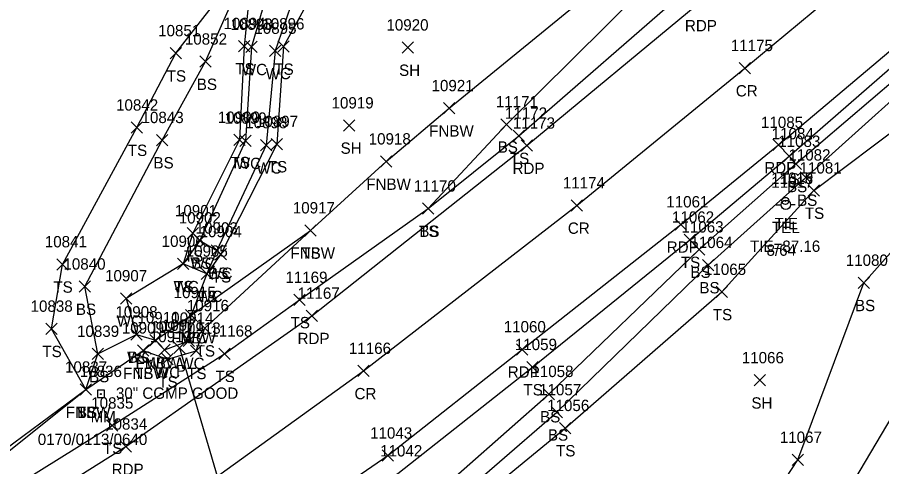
# Model space of a CAD drawing. Extents: x 1475671 to 1477951, y 592661 to 593821.
# Drawn here: x 1476588.2 to 1476740.9, y 593153.9 to 593233.2 of the extents above; entities that cross this region are included whole.
import ezdxf

# ---------------------------------------------------------------- set-up
doc = ezdxf.new("R2010")
doc.units = 0
for name, color, linetype in [('C_A', 7, 'Continuous'), ('C_C', 7, 'Continuous'), ('C_I', 7, 'Continuous'), ('CBP', 7, 'Continuous'), ('D_A', 7, 'Continuous'), ('D_C', 7, 'Continuous'), ('D_I', 7, 'Continuous'), ('D_TIC', 7, 'Continuous'), ('DCP', 7, 'Continuous'), ('L_A', 7, 'Continuous'), ('L_I', 7, 'Continuous'), ('L_TIC', 7, 'Continuous'), ('LAWE', 7, 'Continuous'), ('LELB', 7, 'Continuous'), ('LFNC', 7, 'Continuous'), ('P_A', 7, 'Continuous'), ('P_I', 7, 'Continuous'), ('P_TIC', 7, 'Continuous'), ('PET', 7, 'Continuous'), ('PRC', 7, 'Continuous'), ('S_A', 7, 'Continuous'), ('S_C', 7, 'Continuous'), ('S_I', 7, 'Continuous'), ('SRM', 7, 'Continuous'), ('U_A', 7, 'Continuous'), ('U_C', 7, 'Continuous'), ('U_I', 7, 'Continuous'), ('UP', 7, 'Continuous')]:
    doc.layers.add(name, color=color, linetype=linetype)

msp = doc.modelspace()

# ---------------------------------------------------------------- linework, layer by layer
at = {"layer": 'CBP'}
for radius in [0.625, 0.0833]:
    msp.add_circle((1476723.87, 593200.82), radius, dxfattribs=at)
at = {"layer": 'D_TIC'}
for points in [[(1476615.88, 593173.89), (1476617.88, 593175.89)], [(1476617.88, 593173.89), (1476615.88, 593175.89)]]:
    msp.add_lwpolyline(points, dxfattribs=at)
at = {"layer": 'DCP'}
msp.add_lwpolyline([(1476616.88, 593174.89), (1476630.2, 593129.6)], dxfattribs=at)
at = {"layer": 'L_TIC'}
for points in [[(1476627.33, 593227.14), (1476629.33, 593229.14)], [(1476629.33, 593227.14), (1476627.33, 593229.14)], [(1476628.57, 593227.01), (1476630.57, 593229.01)], [(1476630.57, 593227.01), (1476628.57, 593229.01)], [(1476632.78, 593226.3), (1476634.78, 593228.3)], [(1476634.78, 593226.3), (1476632.78, 593228.3)], [(1476634.23, 593227.07), (1476636.23, 593229.07)], [(1476636.23, 593227.07), (1476634.23, 593229.07)], [(1476656.18, 593226.88), (1476658.18, 593228.88)], [(1476658.18, 593226.88), (1476656.18, 593228.88)], [(1476615.22, 593225.87), (1476617.22, 593227.87)], [(1476617.22, 593225.87), (1476615.22, 593227.87)], [(1476620.5, 593224.4), (1476622.5, 593226.4)], [(1476622.5, 593224.4), (1476620.5, 593226.4)], [(1476663.49, 593216.17), (1476665.49, 593218.17)], [(1476665.49, 593216.17), (1476663.49, 593218.17)], [(1476608.35, 593212.75), (1476610.35, 593214.75)], [(1476610.35, 593212.75), (1476608.35, 593214.75)], [(1476645.84, 593213.13), (1476647.84, 593215.13)], [(1476647.84, 593213.13), (1476645.84, 593215.13)], [(1476673.63, 593213.33), (1476675.63, 593215.33)], [(1476675.63, 593213.33), (1476673.63, 593215.33)], [(1476675.81, 593211.32), (1476677.81, 593213.32)], [(1476677.81, 593211.32), (1476675.81, 593213.32)], [(1476612.85, 593210.55), (1476614.85, 593212.55)], [(1476614.85, 593210.55), (1476612.85, 593212.55)], [(1476626.49, 593210.59), (1476628.49, 593212.59)], [(1476628.49, 593210.59), (1476626.49, 593212.59)], [(1476627.52, 593210.44), (1476629.52, 593212.44)], [(1476629.52, 593210.44), (1476627.52, 593212.44)], [(1476631.16, 593209.64), (1476633.16, 593211.64)], [(1476633.16, 593209.64), (1476631.16, 593211.64)], [(1476633.06, 593209.85), (1476635.06, 593211.85)], [(1476635.06, 593209.85), (1476633.06, 593211.85)], [(1476652.4, 593206.77), (1476654.4, 593208.77)], [(1476654.4, 593206.77), (1476652.4, 593208.77)], [(1476723.55, 593207.7), (1476725.55, 593209.7)], [(1476725.55, 593207.7), (1476723.55, 593209.7)], [(1476724.71, 593206.35), (1476726.71, 593208.35)], [(1476726.71, 593206.35), (1476724.71, 593208.35)], [(1476726.5, 593203.94), (1476728.5, 593205.94)], [(1476728.5, 593203.94), (1476726.5, 593205.94)], [(1476727.9, 593201.65), (1476729.9, 593203.65)], [(1476729.9, 593201.65), (1476727.9, 593203.65)], [(1476659.79, 593198.46), (1476661.79, 593200.46)], [(1476661.79, 593198.46), (1476659.79, 593200.46)], [(1476659.79, 593198.46), (1476661.79, 593200.46)], [(1476661.79, 593198.46), (1476659.79, 593200.46)], [(1476618.26, 593194.1), (1476620.26, 593196.1)], [(1476620.26, 593194.1), (1476618.26, 593196.1)], [(1476639, 593194.61), (1476641, 593196.61)], [(1476641, 593194.61), (1476639, 593196.61)], [(1476639, 593194.61), (1476641, 593196.61)], [(1476641, 593194.61), (1476639, 593196.61)], [(1476619.49, 593192.84), (1476621.49, 593194.84)], [(1476621.49, 593192.84), (1476619.49, 593194.84)], [(1476619.49, 593192.84), (1476621.49, 593194.84)], [(1476621.49, 593192.84), (1476619.49, 593194.84)], [(1476706, 593192.97), (1476708, 593194.97)], [(1476708, 593192.97), (1476706, 593194.97)], [(1476622.48, 593191.05), (1476624.48, 593193.05)], [(1476624.48, 593191.05), (1476622.48, 593193.05)], [(1476622.48, 593191.05), (1476624.48, 593193.05)], [(1476624.48, 593191.05), (1476622.48, 593193.05)], [(1476707.67, 593191.24), (1476709.67, 593193.24)], [(1476709.67, 593191.24), (1476707.67, 593193.24)], [(1476623.18, 593190.42), (1476625.18, 593192.42)], [(1476625.18, 593190.42), (1476623.18, 593192.42)], [(1476595.2, 593188.62), (1476597.2, 593190.62)], [(1476597.2, 593188.62), (1476595.2, 593190.62)], [(1476616.53, 593188.7), (1476618.53, 593190.7)], [(1476618.53, 593188.7), (1476616.53, 593190.7)], [(1476616.53, 593188.7), (1476618.53, 593190.7)], [(1476618.53, 593188.7), (1476616.53, 593190.7)], [(1476616.53, 593188.7), (1476618.53, 593190.7)], [(1476618.53, 593188.7), (1476616.53, 593190.7)], [(1476709.24, 593188.5), (1476711.24, 593190.5)], [(1476711.24, 593188.5), (1476709.24, 593190.5)], [(1476620.73, 593186.97), (1476622.73, 593188.97)], [(1476622.73, 593186.97), (1476620.73, 593188.97)], [(1476620.73, 593186.97), (1476622.73, 593188.97)], [(1476622.73, 593186.97), (1476620.73, 593188.97)], [(1476736.72, 593185.36), (1476738.72, 593187.36)], [(1476738.72, 593185.36), (1476736.72, 593187.36)], [(1476599.14, 593184.69), (1476601.14, 593186.69)], [(1476601.14, 593184.69), (1476599.14, 593186.69)], [(1476711.65, 593183.75), (1476713.65, 593185.75)], [(1476713.65, 593183.75), (1476711.65, 593185.75)], [(1476606.49, 593182.62), (1476608.49, 593184.62)], [(1476608.49, 593182.62), (1476606.49, 593184.62)], [(1476637.09, 593182.34), (1476639.09, 593184.34)], [(1476639.09, 593182.34), (1476637.09, 593184.34)], [(1476617.95, 593179.66), (1476619.95, 593181.66)], [(1476619.95, 593179.66), (1476617.95, 593181.66)], [(1476617.95, 593179.66), (1476619.95, 593181.66)], [(1476619.95, 593179.66), (1476617.95, 593181.66)], [(1476617.95, 593179.66), (1476619.95, 593181.66)], [(1476619.95, 593179.66), (1476617.95, 593181.66)], [(1476593.26, 593177.25), (1476595.26, 593179.25)], [(1476595.26, 593177.25), (1476593.26, 593179.25)], [(1476620.33, 593177.35), (1476622.33, 593179.35)], [(1476622.33, 593177.35), (1476620.33, 593179.35)], [(1476608.32, 593176.24), (1476610.32, 593178.24)], [(1476610.32, 593176.24), (1476608.32, 593178.24)], [(1476608.32, 593176.24), (1476610.32, 593178.24)], [(1476610.32, 593176.24), (1476608.32, 593178.24)], [(1476611.65, 593175.23), (1476613.65, 593177.23)], [(1476613.65, 593175.23), (1476611.65, 593177.23)], [(1476611.65, 593175.23), (1476613.65, 593177.23)], [(1476613.65, 593175.23), (1476611.65, 593177.23)], [(1476617.55, 593175.15), (1476619.55, 593177.15)], [(1476619.55, 593175.15), (1476617.55, 593177.15)], [(1476601.47, 593172.82), (1476603.47, 593174.82)], [(1476603.47, 593172.82), (1476601.47, 593174.82)], [(1476601.47, 593172.82), (1476603.47, 593174.82)], [(1476603.47, 593172.82), (1476601.47, 593174.82)], [(1476609.45, 593173.4), (1476611.45, 593175.4)], [(1476611.45, 593173.4), (1476609.45, 593175.4)], [(1476609.45, 593173.4), (1476611.45, 593175.4)], [(1476611.45, 593173.4), (1476609.45, 593175.4)], [(1476613.24, 593173.55), (1476615.24, 593175.55)], [(1476615.24, 593173.55), (1476613.24, 593175.55)], [(1476618.83, 593173.37), (1476620.83, 593175.37)], [(1476620.83, 593173.37), (1476618.83, 593175.37)], [(1476623.83, 593172.86), (1476625.83, 593174.86)], [(1476625.83, 593172.86), (1476623.83, 593174.86)], [(1476613.74, 593171.88), (1476615.74, 593173.88)], [(1476615.74, 593171.88), (1476613.74, 593173.88)], [(1476678.21, 593170.49), (1476680.21, 593172.49)], [(1476680.21, 593170.49), (1476678.21, 593172.49)], [(1476718.38, 593168.16), (1476720.38, 593170.16)], [(1476720.38, 593168.16), (1476718.38, 593170.16)], [(1476599.34, 593166.51), (1476601.34, 593168.51)], [(1476601.34, 593166.51), (1476599.34, 593168.51)], [(1476599.34, 593166.51), (1476601.34, 593168.51)], [(1476601.34, 593166.51), (1476599.34, 593168.51)], [(1476599.34, 593166.51), (1476601.34, 593168.51)], [(1476601.34, 593166.51), (1476599.34, 593168.51)], [(1476681.12, 593165.73), (1476683.12, 593167.73)], [(1476683.12, 593165.73), (1476681.12, 593167.73)], [(1476682.5, 593162.51), (1476684.5, 593164.51)], [(1476684.5, 593162.51), (1476682.5, 593164.51)], [(1476603.97, 593160.16), (1476605.97, 593162.16)], [(1476605.97, 593160.16), (1476603.97, 593162.16)], [(1476683.96, 593159.73), (1476685.96, 593161.73)], [(1476685.96, 593159.73), (1476683.96, 593161.73)], [(1476725.04, 593154.11), (1476727.04, 593156.11)], [(1476727.04, 593154.11), (1476725.04, 593156.11)]]:
    msp.add_lwpolyline(points, dxfattribs=at)
at = {"layer": 'LAWE'}
for points in [[(1476613.09, 593353.64), (1476628.49, 593336.62), (1476629.68, 593311.25), (1476637.78, 593296.68), (1476643.29, 593273.67), (1476640.66, 593247.23), (1476633.78, 593227.3), (1476632.16, 593210.64), (1476623.48, 593192.05), (1476621.73, 593187.97), (1476618.95, 593180.66)], [(1476607.39, 593350.65), (1476623.84, 593334.1), (1476626.69, 593304.02), (1476631.08, 593291.78), (1476635.24, 593271.58), (1476635.2, 593247.29), (1476629.57, 593228.01), (1476628.52, 593211.44), (1476620.49, 593193.84), (1476617.53, 593189.7), (1476607.49, 593183.62), (1476609.32, 593177.24), (1476612.65, 593176.23), (1476614.24, 593174.55), (1476618.55, 593176.15), (1476618.95, 593180.66)]]:
    msp.add_lwpolyline(points, dxfattribs=at)
at = {"layer": 'LELB'}
for points in [[(1476660.79, 593199.46), (1476674.63, 593214.33), (1476703.92, 593243.37), (1476720.54, 593255.98), (1476751.7, 593282.61), (1476781.77, 593307.79), (1476789.04, 593316.89), (1476807.89, 593333.24), (1476839.71, 593357.28), (1476859.97, 593374.46), (1476882.16, 593391.96), (1476882.87, 593395.08), (1476884.75, 593398.78), (1476886.94, 593401.06), (1476880.92, 593405.09), (1476872.21, 593402.61), (1476869.35, 593406.91), (1476883.46, 593416.6), (1476894.87, 593423.54), (1476922.16, 593439.01), (1476941.74, 593451.3), (1476958.3, 593465.19), (1476973.77, 593478.9)], [(1476525.71, 593116.6), (1476535.99, 593117.47), (1476564.39, 593135.96), (1476604.97, 593161.16), (1476624.83, 593173.86), (1476638.09, 593183.34), (1476660.79, 593199.46), (1476676.81, 593212.32), (1476707.13, 593238.69), (1476723.81, 593252.6), (1476754.14, 593278.44), (1476785.31, 593303.01), (1476812.8, 593326.19), (1476842.99, 593352.59), (1476863.07, 593369.43), (1476886.56, 593389.77), (1476893.66, 593396.85), (1476901.2, 593401.68), (1476921.17, 593422.2)], [(1476564.12, 593090.41), (1476582.11, 593100.23), (1476611.48, 593121.39), (1476618.84, 593125.52), (1476623.35, 593128.86), (1476625.72, 593132.79), (1476629.36, 593135.67), (1476655.41, 593152.72), (1476679.21, 593171.49), (1476707, 593193.97), (1476724.55, 593208.7), (1476750.98, 593231.69), (1476770.54, 593248.26), (1476798.66, 593272.17), (1476825.82, 593296.2), (1476846.6, 593313.13), (1476851.35, 593312.9), (1476856.13, 593310.72)], [(1476631.97, 593309.46), (1476640.29, 593298.07), (1476646.83, 593274.76), (1476645.56, 593246.81), (1476635.23, 593228.07), (1476634.06, 593210.85), (1476624.18, 593191.42), (1476621.73, 593187.97), (1476617.53, 593189.7)], [(1476634.2, 593131.94), (1476659.65, 593146.95), (1476682.12, 593166.73), (1476708.67, 593192.24), (1476725.71, 593207.35), (1476752.23, 593229.94), (1476771.82, 593246.25), (1476799.29, 593271), (1476827.81, 593293.85), (1476847.08, 593308.34), (1476849.31, 593306.85)], [(1476637.68, 593129.04), (1476661.51, 593144.5), (1476683.5, 593163.51), (1476710.24, 593189.5), (1476727.5, 593204.94), (1476753.67, 593228.48), (1476773.33, 593243.8), (1476800.69, 593269.42), (1476829.36, 593291.34), (1476849.31, 593306.85)], [(1476678.64, 593101), (1476705.61, 593123.8), (1476726.04, 593155.11), (1476737.72, 593186.36), (1476761.68, 593213.28), (1476787.87, 593223.87), (1476810.46, 593252.94), (1476833.91, 593283.76), (1476845.71, 593295.92)], [(1476656.22, 593100.09), (1476649.63, 593114.77), (1476646.3, 593117.93), (1476646.01, 593122.62), (1476642.33, 593128.21), (1476662.9, 593142.59), (1476684.96, 593160.73), (1476712.65, 593184.75), (1476728.9, 593202.65), (1476756.29, 593223.25), (1476776.28, 593240.54), (1476803.27, 593265.83), (1476831.65, 593287.61)], [(1476678.64, 593101), (1476711, 593115.17), (1476731.22, 593143.42), (1476747.62, 593171.01), (1476767.46, 593198.64), (1476796.55, 593210.23), (1476815.09, 593241.8), (1476843.63, 593278.61)], [(1476600.34, 593167.51), (1476594.26, 593178.25), (1476596.2, 593189.62), (1476609.35, 593213.75), (1476616.22, 593226.87), (1476629.97, 593244.55), (1476628.33, 593228.14), (1476627.49, 593211.59), (1476619.26, 593195.1), (1476617.53, 593189.7)], [(1476602.47, 593173.82), (1476600.14, 593185.69), (1476613.85, 593211.55), (1476621.5, 593225.4), (1476629.97, 593244.55)], [(1476610.45, 593174.4), (1476614.74, 593172.88), (1476619.83, 593174.37), (1476621.33, 593178.35), (1476640, 593195.61)], [(1476620.49, 593193.84), (1476623.48, 593192.05)], [(1476498.59, 593101.6), (1476505.69, 593104.75), (1476515.32, 593111.26), (1476518.29, 593115.4), (1476532.21, 593122.02), (1476550.06, 593131.97), (1476556.63, 593136.22), (1476579.62, 593152.26), (1476600.34, 593167.51), (1476602.47, 593173.82), (1476609.32, 593177.24)]]:
    msp.add_lwpolyline(points, dxfattribs=at)
at = {"layer": 'LFNC'}
msp.add_lwpolyline([(1476458.99, 593083.01), (1476499.73, 593099.84), (1476506.4, 593103.47), (1476506.74, 593103.7), (1476516.66, 593109.69), (1476525.71, 593116.6), (1476534.13, 593120.72), (1476545.43, 593126.64), (1476563.76, 593138.28), (1476600.34, 593167.51), (1476610.45, 593174.4), (1476612.65, 593176.23), (1476618.95, 593180.66), (1476640, 593195.61), (1476653.4, 593207.77), (1476664.49, 593217.17), (1476691.69, 593239.4), (1476702.63, 593247.23), (1476709.5, 593251.9), (1476716.55, 593257.09), (1476733.12, 593270.47), (1476759.81, 593293.37)], dxfattribs=at)
at = {"layer": 'P_TIC'}
for points in [[(1476715.69, 593223.25), (1476717.69, 593225.25)], [(1476717.69, 593223.25), (1476715.69, 593225.25)], [(1476677.21, 593209.57), (1476679.21, 593211.57)], [(1476679.21, 593209.57), (1476677.21, 593211.57)], [(1476721.66, 593209.69), (1476723.66, 593211.69)], [(1476723.66, 593209.69), (1476721.66, 593211.69)], [(1476686.02, 593199.01), (1476688.02, 593201.01)], [(1476688.02, 593199.01), (1476686.02, 593201.01)], [(1476704.43, 593195.67), (1476706.43, 593197.67)], [(1476706.43, 593195.67), (1476704.43, 593197.67)], [(1476639.25, 593179.54), (1476641.25, 593181.54)], [(1476641.25, 593179.54), (1476639.25, 593181.54)], [(1476676.37, 593173.62), (1476678.37, 593175.62)], [(1476678.37, 593173.62), (1476676.37, 593175.62)], [(1476648.36, 593169.81), (1476650.36, 593171.81)], [(1476650.36, 593169.81), (1476648.36, 593171.81)], [(1476606.43, 593156.45), (1476608.43, 593158.45)], [(1476608.43, 593156.45), (1476606.43, 593158.45)], [(1476652.65, 593154.86), (1476654.65, 593156.86)], [(1476654.65, 593154.86), (1476652.65, 593156.86)]]:
    msp.add_lwpolyline(points, dxfattribs=at)
at = {"layer": 'PET'}
for points in [[(1476459.25, 593078.48), (1476508.39, 593100.17), (1476518.15, 593105.13), (1476565.38, 593131.07), (1476607.43, 593157.45), (1476640.25, 593180.54), (1476678.21, 593210.57), (1476708.64, 593235.75), (1476725.67, 593249.83), (1476755.84, 593275.3), (1476786.3, 593300.73), (1476814.32, 593324.28), (1476845.05, 593350.02), (1476865.02, 593366.82), (1476897.04, 593395.14), (1476922.98, 593419.08), (1476952.36, 593443.37)], [(1476493.61, 593061.9), (1476518.9, 593073.26), (1476550.12, 593088.22), (1476579.1, 593105.35), (1476612.57, 593127.79), (1476627.64, 593138.01), (1476653.65, 593155.86), (1476677.37, 593174.62), (1476705.43, 593196.67), (1476722.66, 593210.69), (1476749.61, 593233.45), (1476768.81, 593249.96), (1476797.5, 593274.02), (1476824.82, 593297.55), (1476845, 593315.29), (1476868.19, 593333.86), (1476888.66, 593352.98), (1476918.01, 593376.95), (1476944.23, 593398.87), (1476967.73, 593418.7), (1476998.53, 593444.47)]]:
    msp.add_lwpolyline(points, dxfattribs=at)
at = {"layer": 'PRC'}
msp.add_lwpolyline([(1476461.98, 593064.62), (1476520.7, 593090.52), (1476540.79, 593101.34), (1476577.67, 593121.61), (1476614.51, 593145.69), (1476649.36, 593170.81), (1476687.02, 593200.01), (1476716.69, 593224.25), (1476733.58, 593238.31), (1476760.9, 593261.21), (1476795.35, 593290.14), (1476823.06, 593313.51), (1476854.07, 593339.52), (1476875.7, 593357.51), (1476907.01, 593384.08), (1476934.06, 593407.68), (1476963.46, 593432.81)], dxfattribs=at)
at = {"layer": 'SRM'}
for p, q in [((1476603.65, 593167.39), (1476602.4, 593167.39)), ((1476602.4, 593167.39), (1476602.4, 593166.14)), ((1476603.65, 593167.39), (1476602.4, 593167.39)), ((1476602.4, 593167.39), (1476602.4, 593166.14)), ((1476603.65, 593166.14), (1476603.65, 593167.39)), ((1476603.65, 593166.14), (1476603.65, 593167.39)), ((1476602.4, 593166.14), (1476603.65, 593166.14)), ((1476602.4, 593166.14), (1476603.65, 593166.14))]:
    msp.add_line(p, q, dxfattribs=at)
msp.add_circle((1476603, 593166.73), 0.0833, dxfattribs=at)
at = {"layer": 'UP'}
for p, q in [((1476722.27, 593200.13), (1476723.1, 593200.13)), ((1476723.93, 593200.13), (1476723.93, 593200.13)), ((1476725.6, 593200.13), (1476724.76, 593200.13)), ((1476724.76, 593200.13), (1476724.76, 593200.13)), ((1476725.6, 593200.13), (1476725.6, 593200.13))]:
    msp.add_line(p, q, dxfattribs=at)
msp.add_circle((1476723.93, 593200.13), 0.833, dxfattribs=at)

# ---------------------------------------------------------------- texts
at = {"layer": 'C_A'}
msp.add_text('TIE', height=2, dxfattribs=at).set_placement((1476721.95, 593195.82))
at = {"layer": 'C_C'}
msp.add_text('TIE=87.16', height=2, dxfattribs=at).set_placement((1476717.61, 593191.82))
at = {"layer": 'C_I'}
msp.add_text('11018', height=2, dxfattribs=at).set_placement((1476721.34, 593203.82))
at = {"layer": 'D_A'}
msp.add_text('P', height=2, dxfattribs=at).set_placement((1476616.26, 593169.89))
at = {"layer": 'D_C'}
msp.add_text('30" CGMP GOOD', height=2, dxfattribs=at).set_placement((1476605.66, 593165.89))
at = {"layer": 'D_I'}
msp.add_text('10971', height=2, dxfattribs=at).set_placement((1476613.78, 593177.89))
at = {"layer": 'L_A'}
for s, p in [('TS', (1476626.74, 593223.14)), ('WC', (1476627.88, 593223.01)), ('TS', (1476633.64, 593223.07)), ('TS', (1476614.63, 593221.87)), ('WC', (1476632.09, 593222.3)), ('SH', (1476655.66, 593222.88)), ('BS', (1476619.94, 593220.4)), ('FNBW', (1476660.97, 593212.17)), ('BS', (1476673.07, 593209.33)), ('TS', (1476607.76, 593208.75)), ('SH', (1476645.33, 593209.13)), ('BS', (1476612.29, 593206.55)), ('TS', (1476625.9, 593206.59)), ('WC', (1476626.83, 593206.44)), ('TS', (1476675.22, 593207.32)), ('WC', (1476630.47, 593205.64)), ('TS', (1476632.47, 593205.85)), ('TS', (1476722.96, 593203.7)), ('FNBW', (1476649.87, 593202.77)), ('BS', (1476724.16, 593202.35)), ('BS', (1476725.94, 593199.94)), ('TS', (1476727.31, 593197.65)), ('TS', (1476659.2, 593194.46)), ('BS', (1476659.23, 593194.46)), ('TS', (1476617.67, 593190.1)), ('FNBW', (1476636.47, 593190.61)), ('TS', (1476638.41, 593190.61)), ('WC', (1476618.8, 593188.84)), ('BS', (1476618.94, 593188.84)), ('TS', (1476705.41, 593188.97)), ('WC', (1476621.79, 593187.05)), ('BS', (1476621.93, 593187.05)), ('TS', (1476622.59, 593186.42)), ('BS', (1476707.11, 593187.24)), ('TS', (1476594.61, 593184.62)), ('WC', (1476615.84, 593184.7)), ('TS', (1476615.94, 593184.7)), ('TS', (1476615.94, 593184.7)), ('BS', (1476708.68, 593184.5)), ('WC', (1476620.03, 593182.97)), ('TS', (1476620.13, 593182.97)), ('BS', (1476598.59, 593180.69)), ('BS', (1476736.16, 593181.36)), ('TS', (1476711.06, 593179.75)), ('WC', (1476605.8, 593178.62)), ('TS', (1476636.5, 593178.34)), ('FNBW', (1476615.43, 593175.66)), ('WC', (1476617.26, 593175.66)), ('WC', (1476617.26, 593175.66)), ('TS', (1476592.67, 593173.25)), ('TS', (1476619.74, 593173.35)), ('WC', (1476607.63, 593172.24)), ('BS', (1476607.76, 593172.24)), ('FNBW', (1476609.13, 593171.23)), ('WC', (1476610.96, 593171.23)), ('WC', (1476616.85, 593171.15)), ('BS', (1476600.91, 593168.82)), ('BS', (1476600.91, 593168.82)), ('FNBW', (1476606.93, 593169.4)), ('TS', (1476608.86, 593169.4)), ('WC', (1476612.55, 593169.55)), ('TS', (1476618.23, 593169.37)), ('TS', (1476623.24, 593168.86)), ('TS', (1476613.15, 593167.88)), ('TS', (1476677.62, 593166.49)), ('SH', (1476717.87, 593164.16)), ('FNBW', (1476596.81, 593162.51)), ('TS', (1476598.75, 593162.51)), ('BS', (1476598.78, 593162.51)), ('BS', (1476680.56, 593161.73)), ('BS', (1476681.94, 593158.51)), ('TS', (1476603.38, 593156.16)), ('TS', (1476683.37, 593155.73))]:
    msp.add_text(s, height=2, dxfattribs=at).set_placement(p)
at = {"layer": 'L_I'}
for s, p in [('10894', (1476624.66, 593231.14)), ('10893', (1476625.9, 593231.01)), ('10896', (1476631.51, 593231.07)), ('10920', (1476653.42, 593230.88)), ('10851', (1476613.11, 593229.87)), ('10895', (1476630.11, 593230.3)), ('10852', (1476617.83, 593228.4)), ('10921', (1476661.39, 593220.17)), ('10919', (1476643.73, 593217.13)), ('11171', (1476672.74, 593217.33)), ('10842', (1476605.68, 593216.75)), ('10843', (1476610.18, 593214.55)), ('10900', (1476623.65, 593214.59)), ('10899', (1476624.84, 593214.44)), ('10897', (1476630.39, 593213.85)), ('11172', (1476674.36, 593215.32)), ('10898', (1476628.49, 593213.64)), ('11084', (1476721.45, 593211.7)), ('10918', (1476650.29, 593210.77)), ('11083', (1476722.61, 593210.35)), ('11082', (1476724.4, 593207.94)), ('11081', (1476726.37, 593205.65)), ('11170', (1476658.25, 593202.46)), ('11170', (1476658.25, 593202.46)), ('10917', (1476636.89, 593198.61)), ('10917', (1476636.89, 593198.61)), ('10901', (1476616.08, 593198.1)), ('10902', (1476616.75, 593196.84)), ('10902', (1476616.75, 593196.84)), ('11062', (1476703.85, 593196.97)), ('10903', (1476619.74, 593195.05)), ('10903', (1476619.74, 593195.05)), ('10904', (1476620.43, 593194.42)), ('11063', (1476705.52, 593195.24)), ('10841', (1476593.1, 593192.62)), ('10906', (1476613.73, 593192.7)), ('10906', (1476613.73, 593192.7)), ('10906', (1476613.73, 593192.7)), ('11064', (1476707.09, 593192.5)), ('10905', (1476617.98, 593190.97)), ('10905', (1476617.98, 593190.97)), ('10840', (1476596.39, 593188.69)), ('11080', (1476734.53, 593189.36)), ('10907', (1476603.74, 593186.62)), ('11065', (1476709.5, 593187.75)), ('11169', (1476635.58, 593186.34)), ('10915', (1476615.85, 593183.66)), ('10915', (1476615.85, 593183.66)), ('10915', (1476615.85, 593183.66)), ('10838', (1476590.59, 593181.25)), ('10916', (1476618.18, 593181.35)), ('10908', (1476605.57, 593180.24)), ('10908', (1476605.57, 593180.24)), ('10910', (1476609.46, 593179.23)), ('10910', (1476609.46, 593179.23)), ('10914', (1476615.44, 593179.15)), ('10909', (1476606.7, 593177.4)), ('10909', (1476606.7, 593177.4)), ('10911', (1476611.71, 593177.55)), ('10913', (1476616.72, 593177.37)), ('10839', (1476598.79, 593176.82)), ('10839', (1476598.79, 593176.82)), ('10912', (1476611.64, 593175.88)), ('11168', (1476622.33, 593176.86)), ('11059', (1476676.1, 593174.49)), ('11066', (1476716.17, 593172.16)), ('10837', (1476596.67, 593170.51)), ('10837', (1476596.67, 593170.51)), ('10837', (1476596.67, 593170.51)), ('11058', (1476679.02, 593169.73)), ('11057', (1476680.39, 593166.51)), ('10835', (1476601.3, 593164.16)), ('11056', (1476681.8, 593163.73)), ('11067', (1476722.89, 593158.11)), ('11042', (1476652.31, 593155.72))]:
    msp.add_text(s, height=2, dxfattribs=at).set_placement(p)
at = {"layer": 'P_A'}
for s, p in [('RDP', (1476706.13, 593230.75)), ('CR', (1476715.12, 593219.25)), ('RDP', (1476675.69, 593205.57)), ('RDP', (1476720.15, 593205.69)), ('CR', (1476685.46, 593195.01)), ('RDP', (1476702.92, 593191.67)), ('RDP', (1476637.73, 593175.54)), ('RDP', (1476674.85, 593169.62)), ('CR', (1476647.79, 593165.81)), ('RDP', (1476604.91, 593152.45))]:
    msp.add_text(s, height=2, dxfattribs=at).set_placement(p)
at = {"layer": 'P_I'}
for s, p in [('11175', (1476714.23, 593227.25)), ('11173', (1476675.75, 593213.57)), ('11085', (1476719.56, 593213.69)), ('11174', (1476684.57, 593203.01)), ('11061', (1476702.84, 593199.67)), ('11167', (1476637.74, 593183.54)), ('11060', (1476674.13, 593177.62)), ('11166', (1476646.8, 593173.81)), ('10834', (1476603.76, 593160.45)), ('11043', (1476650.54, 593158.86))]:
    msp.add_text(s, height=2, dxfattribs=at).set_placement(p)
at = {"layer": 'S_A'}
msp.add_text('MM', height=2, dxfattribs=at).set_placement((1476601.19, 593161.74))
at = {"layer": 'S_C'}
msp.add_text('0170/0113/0640', height=2, dxfattribs=at).set_placement((1476591.86, 593157.74))
at = {"layer": 'S_I'}
msp.add_text('10836', height=2, dxfattribs=at).set_placement((1476599.28, 593169.74))
at = {"layer": 'U_A'}
msp.add_text('TEL', height=2, dxfattribs=at).set_placement((1476721.49, 593195.13))
at = {"layer": 'U_C'}
msp.add_text('8/64', height=2, dxfattribs=at).set_placement((1476720.54, 593191.13))
at = {"layer": 'U_I'}
msp.add_text('11017', height=2, dxfattribs=at).set_placement((1476721.39, 593203.13))

doc.saveas('drawing.dxf')
